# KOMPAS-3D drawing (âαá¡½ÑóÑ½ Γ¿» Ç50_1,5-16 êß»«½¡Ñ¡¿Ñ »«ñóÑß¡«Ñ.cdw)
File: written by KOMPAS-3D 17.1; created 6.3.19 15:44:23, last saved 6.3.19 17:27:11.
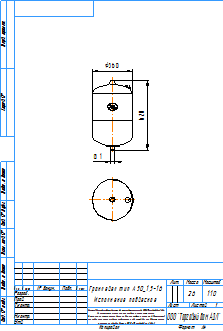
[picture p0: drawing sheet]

Sheet 1: A4, portrait

Title block, sheet 1: name: Гранлевел тип А50_1,5-16 / Исполнение подвесное; material: Сталь 10  ГОСТ 1050-88; mass: 26; sheets: 1; sheet format: A4; stored path: C:\Users\kka\KOMPAS_Work\!Trash\ГРАНЛЕВЕЛ тип А Расширительный бак\KOMPAS 2D\Гранлевел тип А100_1,5-16.cdw

Views: Вид 1, Проекционный вид 2
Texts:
  kka
  adl
  Рама для чертежей
  Лит-Масса-Масштаб
  Материал-Предприятие
  Масштаб
  Изм.
  Лист
  № докум.
  Подп.
  Дата
  Лит.
  Разраб.
  Пров.
  Т.контр.
  Листов
  Внимание! Данный продукт является объектом авторского права ООО «Торговый Дом АДЛ».
  Запрещается изменение, копирование, распространение
  (в том числе путем копирования на другие сайты и ресурсы в Интернете)
  или любое иное использование информации и объектов без предварительного
  согласия правообладателя (ООО «Торговый Дом АДЛ»).
  Н.контр.
  Утв.
  ООО "Торговый дом АДЛ"
  Изменение
  Номер документа
  Подпись
  Обозначение документа
  Наименование изделия
  Масса изделия по ГОСТ 2.109-73
  Порядковый номер листа
  Общее количество листов в документе
  Характер работы, выполненной лицом, подписавшим документ
  Наименование или индекс предприятия, выпускающего документ
  Инв. № подл.
  Подп. и дата
  Взам. инв. №
  Инв. № дубл.
  Инвентарный номер подлинника по ГОСТ 2.501-68
  Подпись принявшего подлинник в отдел технической документации
  Инвентарный номер подлинника, взамен которого выпущен данный подлинник
  Инвентарный номер дубликата по ГОСТ 2.502-68
  Подпись принявшего дубликат в отдел технической документации
  Справ. №
  Перв. примен.
  Обозначение документа, взамен или на основании которого выпущен данный документ
  Обозначение документа, в котором впервые записан данный документ
  Подпись лица, копировавшего чертеж
  Обозначение формата листа
  !Рама для чертежа
Dimensions and other numbers on the sheet: 620; 360; 1; 1:10; 26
